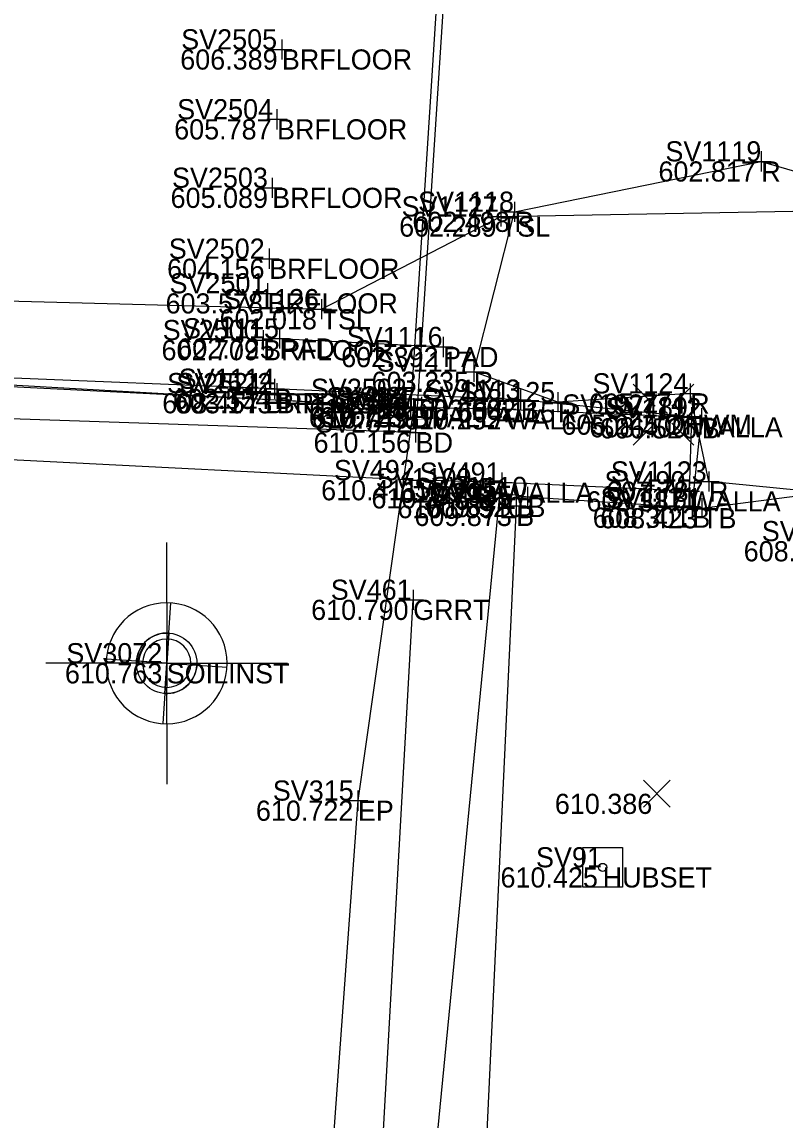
# Model space of a CAD drawing. Extents: x -2 to 1979875, y -2 to 232027.
# Drawn here: x 1978775.86 to 1978794.79, y 231234.17 to 231261.41 of the extents above; entities that cross this region are included whole.
import ezdxf

# ---------------------------------------------------------------- set-up
doc = ezdxf.new("R2010")
doc.units = 0
for name, color, linetype in [('_CIVIL_CONSTRUCTION', 7, 'Continuous'), ('BR_X_SV_Abut', 7, 'Continuous'), ('BR_X_SV_Deck_Floor_Text', 7, 'Continuous'), ('BR_X_SV_Deck_Top', 7, 'Continuous'), ('BR_X_SV_Deck_Top_Text', 7, 'Continuous'), ('DR_X_Erosion_Control', 7, 'Continuous'), ('GE_P_Alignment', 7, 'Continuous'), ('GE_P_Alignment_1000_Stations', 7, 'Continuous'), ('GE_P_Alignment_500_Stations', 7, 'Continuous'), ('GE_X_Alignment', 7, 'Continuous'), ('GE_X_Alignment_1000_Stations', 7, 'Continuous'), ('GE_X_Alignment_100_Curve_Data', 7, 'Continuous'), ('GE_X_Alignment_100_Stations', 7, 'Continuous'), ('GT_Project_Soil_Boring', 7, 'Continuous'), ('HY_X_Water_Edge', 7, 'Continuous'), ('RD_X_Concrete_Pad', 7, 'Continuous'), ('SC_Scratch1', 7, 'Continuous'), ('SV_P_Control_Cells_Set', 7, 'Continuous'), ('SV_X_Control_Cells_Found', 7, 'Continuous'), ('SV_X_Random_Point', 7, 'Continuous'), ('SV_X_Toe_of_Slope', 7, 'Continuous'), ('SV_X_Top_of_Bank', 7, 'Continuous')]:
    doc.layers.add(name, color=color, linetype=linetype)

msp = doc.modelspace()

# ---------------------------------------------------------------- linework, layer by layer
at = {"layer": 'BR_X_SV_Abut'}
for p, q in [((1978761.383, 231253.071), (1978785.768, 231251.859)), ((1978761.397, 231251.268), (1978785.698, 231250.046))]:
    msp.add_line(p, q, dxfattribs=at)
msp.add_lwpolyline([(1978785.768, 231251.859), (1978787.866, 231251.803), (1978792.465, 231251.608), (1978792.413, 231249.77), (1978787.767, 231249.984), (1978785.698, 231250.046)], dxfattribs=at)
at = {"layer": 'BR_X_SV_Deck_Top'}
msp.add_lwpolyline([(1978761.339, 231252.043), (1978764.257, 231294.289), (1978788.348, 231293.277), (1978785.624, 231251.227)], close=True, dxfattribs=at)
at = {"layer": 'DR_X_Erosion_Control'}
msp.add_lwpolyline([(1978787.067, 231252.736), (1978788.074, 231256.704), (1978794.199, 231257.953), (1978799.369, 231256.456), (1978800.674, 231252.04), (1978797.344, 231249.578), (1978792.901, 231250.012), (1978792.436, 231252.197), (1978789.154, 231251.981)], close=True, dxfattribs=at)
at = {"layer": 'GE_P_Alignment'}
msp.add_line((1978782.12, 231252.312), (1978764.845, 231253.02), dxfattribs=at)
for points in [[(1978761.807, 231253.072), (1978774.411, 231252.478), (1978785.5, 231251.852)], [(1978787.063, 231249.844), (1978788.4, 231249.628), (1978792.488, 231249.365), (1978792.72, 231251.581), (1978788.23, 231252.041), (1978782.12, 231252.312)], [(1978788.119, 231249.408), (1978786.943, 231224.352), (1978784.459, 231203.181), (1978783.148, 231179.495), (1978781.259, 231158.933), (1978779.831, 231135.814), (1978779.399, 231114.976), (1978780.51, 231101.208), (1978780.469, 231098.542), (1978778.925, 231080.086), (1978777.811, 231054.63), (1978776.389, 231030.876)]]:
    msp.add_lwpolyline(points, dxfattribs=at)
at = {"layer": 'GE_P_Alignment_1000_Stations'}
msp.add_lwpolyline([(1978779.18, 231099.769), (1978777.975, 231123.065), (1978779.192, 231147.605), (1978781.012, 231172.97), (1978782.386, 231197.771), (1978784.253, 231223.721), (1978785.562, 231247.078)], dxfattribs=at)
at = {"layer": 'GE_X_Alignment_1000_Stations'}
for points in [[(1978787.697, 231292.411), (1978786.77, 231271.728), (1978785.515, 231252.063)], [(1978785.568, 231251.827), (1978784.19, 231242.096), (1978782.784, 231222.648), (1978782.32, 231202.663), (1978780.702, 231177.057), (1978778.946, 231150.803), (1978777.805, 231126.797), (1978776.986, 231106.931), (1978775.705, 231085.257), (1978774.572, 231063.753), (1978773.517, 231041.76), (1978772.029, 231016.51), (1978770.7, 230994.507), (1978769.257, 230972.092), (1978767.73, 230948.595), (1978766.192, 230924.232), (1978764.603, 230899.039), (1978762.827, 230873.547), (1978761.273, 230848.668), (1978759.848, 230822.744), (1978759.345, 230799.915), (1978760.114, 230777.862), (1978762.938, 230755.551), (1978769.839, 230729.514)]]:
    msp.add_lwpolyline(points, dxfattribs=at)
at = {"layer": 'GE_X_Alignment_100_Curve_Data'}
for p, q in [((1978782.305, 231260.981), (1978782.305, 231260.481)), ((1978782.055, 231260.731), (1978782.555, 231260.731)), ((1978782.305, 231260.731), (1978782.305, 231260.731)), ((1978782.185, 231259.248), (1978782.185, 231258.748)), ((1978781.935, 231258.998), (1978782.435, 231258.998)), ((1978782.185, 231258.998), (1978782.185, 231258.998)), ((1978794.199, 231258.203), (1978794.199, 231257.703)), ((1978793.949, 231257.953), (1978794.449, 231257.953)), ((1978794.199, 231257.953), (1978794.199, 231257.953)), ((1978782.066, 231257.549), (1978782.066, 231257.049)), ((1978781.816, 231257.299), (1978782.316, 231257.299)), ((1978782.066, 231257.299), (1978782.066, 231257.299)), ((1978787.737, 231256.836), (1978787.737, 231256.336)), ((1978787.824, 231256.704), (1978788.324, 231256.704)), ((1978788.074, 231256.954), (1978788.074, 231256.454)), ((1978788.074, 231256.704), (1978788.074, 231256.704)), ((1978787.487, 231256.586), (1978787.987, 231256.586)), ((1978787.737, 231256.586), (1978787.737, 231256.586)), ((1978781.99, 231255.789), (1978781.99, 231255.289)), ((1978781.74, 231255.539), (1978782.24, 231255.539)), ((1978781.99, 231255.539), (1978781.99, 231255.539)), ((1978781.951, 231254.93), (1978781.951, 231254.43)), ((1978781.701, 231254.68), (1978782.201, 231254.68)), ((1978781.951, 231254.68), (1978781.951, 231254.68)), ((1978783.289, 231254.537), (1978783.289, 231254.037)), ((1978783.039, 231254.287), (1978783.539, 231254.287)), ((1978783.289, 231254.287), (1978783.289, 231254.287)), ((1978781.841, 231253.77), (1978781.841, 231253.27)), ((1978782.248, 231253.813), (1978782.248, 231253.313)), ((1978781.591, 231253.52), (1978782.091, 231253.52)), ((1978781.841, 231253.52), (1978781.841, 231253.52)), ((1978781.998, 231253.563), (1978782.498, 231253.563)), ((1978782.248, 231253.563), (1978782.248, 231253.563)), ((1978786.305, 231253.599), (1978786.305, 231253.099)), ((1978786.055, 231253.349), (1978786.555, 231253.349)), ((1978786.305, 231253.349), (1978786.305, 231253.349)), ((1978787.067, 231252.986), (1978787.067, 231252.486)), ((1978786.817, 231252.736), (1978787.317, 231252.736)), ((1978787.067, 231252.736), (1978787.067, 231252.736)), ((1978781.89, 231252.454), (1978781.89, 231251.954)), ((1978782.12, 231252.562), (1978782.12, 231252.062)), ((1978782.178, 231252.453), (1978782.178, 231251.953)), ((1978792.436, 231252.447), (1978792.436, 231251.947)), ((1978781.64, 231252.204), (1978782.14, 231252.204)), ((1978781.87, 231252.312), (1978782.37, 231252.312)), ((1978781.89, 231252.204), (1978781.89, 231252.204)), ((1978781.928, 231252.203), (1978782.428, 231252.203)), ((1978782.12, 231252.312), (1978782.12, 231252.312)), ((1978782.178, 231252.203), (1978782.178, 231252.203)), ((1978785.5, 231252.102), (1978785.5, 231251.602)), ((1978785.515, 231252.313), (1978785.515, 231251.813)), ((1978785.568, 231252.077), (1978785.568, 231251.577)), ((1978785.768, 231252.109), (1978785.768, 231251.609)), ((1978788.23, 231252.291), (1978788.23, 231251.791)), ((1978789.154, 231252.231), (1978789.154, 231251.731)), ((1978792.186, 231252.197), (1978792.686, 231252.197)), ((1978792.436, 231252.197), (1978792.436, 231252.197)), ((1978785.25, 231251.852), (1978785.75, 231251.852)), ((1978785.265, 231252.063), (1978785.765, 231252.063)), ((1978785.318, 231251.827), (1978785.818, 231251.827)), ((1978785.5, 231251.852), (1978785.5, 231251.852)), ((1978785.515, 231252.063), (1978785.515, 231252.063)), ((1978785.518, 231251.859), (1978786.018, 231251.859)), ((1978785.568, 231251.827), (1978785.568, 231251.827)), ((1978785.768, 231251.859), (1978785.768, 231251.859)), ((1978787.616, 231251.803), (1978788.116, 231251.803)), ((1978787.866, 231252.053), (1978787.866, 231251.553)), ((1978787.866, 231251.803), (1978787.866, 231251.803)), ((1978787.98, 231252.041), (1978788.48, 231252.041)), ((1978788.23, 231252.041), (1978788.23, 231252.041)), ((1978788.904, 231251.981), (1978789.404, 231251.981)), ((1978789.154, 231251.981), (1978789.154, 231251.981)), ((1978792.465, 231251.858), (1978792.465, 231251.358)), ((1978792.72, 231251.831), (1978792.72, 231251.331)), ((1978792.215, 231251.608), (1978792.715, 231251.608)), ((1978792.465, 231251.608), (1978792.465, 231251.608)), ((1978792.47, 231251.581), (1978792.97, 231251.581)), ((1978792.72, 231251.581), (1978792.72, 231251.581)), ((1978785.624, 231251.477), (1978785.624, 231250.977)), ((1978785.374, 231251.227), (1978785.874, 231251.227)), ((1978785.624, 231251.227), (1978785.624, 231251.227)), ((1978785.698, 231250.296), (1978785.698, 231249.796)), ((1978787.767, 231250.234), (1978787.767, 231249.734)), ((1978792.901, 231250.262), (1978792.901, 231249.762)), ((1978785.448, 231250.046), (1978785.948, 231250.046)), ((1978785.698, 231250.046), (1978785.698, 231250.046)), ((1978787.063, 231250.094), (1978787.063, 231249.594)), ((1978787.517, 231249.984), (1978788.017, 231249.984)), ((1978787.767, 231249.984), (1978787.767, 231249.984)), ((1978792.413, 231250.02), (1978792.413, 231249.52)), ((1978792.651, 231250.012), (1978793.151, 231250.012)), ((1978792.901, 231250.012), (1978792.901, 231250.012)), ((1978786.813, 231249.844), (1978787.313, 231249.844)), ((1978787.063, 231249.844), (1978787.063, 231249.844)), ((1978787.694, 231249.851), (1978787.694, 231249.351)), ((1978788.119, 231249.658), (1978788.119, 231249.158)), ((1978788.15, 231249.628), (1978788.65, 231249.628)), ((1978788.4, 231249.878), (1978788.4, 231249.378)), ((1978788.4, 231249.628), (1978788.4, 231249.628)), ((1978792.163, 231249.77), (1978792.663, 231249.77)), ((1978792.413, 231249.77), (1978792.413, 231249.77)), ((1978787.444, 231249.601), (1978787.944, 231249.601)), ((1978787.694, 231249.601), (1978787.694, 231249.601)), ((1978787.869, 231249.408), (1978788.369, 231249.408)), ((1978788.119, 231249.408), (1978788.119, 231249.408)), ((1978792.238, 231249.365), (1978792.738, 231249.365)), ((1978792.479, 231249.351), (1978792.979, 231249.351)), ((1978792.488, 231249.615), (1978792.488, 231249.115)), ((1978792.488, 231249.365), (1978792.488, 231249.365)), ((1978792.729, 231249.601), (1978792.729, 231249.101)), ((1978792.729, 231249.351), (1978792.729, 231249.351)), ((1978785.562, 231247.328), (1978785.562, 231246.828)), ((1978785.312, 231247.078), (1978785.812, 231247.078)), ((1978785.562, 231247.078), (1978785.562, 231247.078)), ((1978784.19, 231242.346), (1978784.19, 231241.846)), ((1978783.94, 231242.096), (1978784.44, 231242.096)), ((1978784.19, 231242.096), (1978784.19, 231242.096))]:
    msp.add_line(p, q, dxfattribs=at)
at = {"layer": 'GT_Project_Soil_Boring'}
for p, q in [((1978779.449, 231245.503), (1978779.549, 231247)), ((1978779.499, 231246.251), (1978779.449, 231245.503)), ((1978779.449, 231245.503), (1978777.952, 231245.603)), ((1978779.449, 231245.503), (1978778.701, 231245.553)), ((1978779.449, 231245.503), (1978779.349, 231244.006)), ((1978779.399, 231244.755), (1978779.449, 231245.503)), ((1978779.449, 231245.503), (1978780.946, 231245.403)), ((1978779.449, 231245.503), (1978780.197, 231245.453))]:
    msp.add_line(p, q, dxfattribs=at)
msp.add_circle((1978779.449, 231245.503), 0.75, dxfattribs=at)
for start, end in [(86.1708, 176.1708), (266.1708, 356.1708)]:
    msp.add_arc((1978779.449, 231245.503), 0.75, start, end, dxfattribs=at)
at = {"layer": 'HY_X_Water_Edge'}
msp.add_lwpolyline([(1978710.396, 231262.363), (1978725.371, 231260.246), (1978739.363, 231256.715), (1978742.039, 231254.081), (1978754.512, 231255.046), (1978783.289, 231254.287), (1978787.737, 231256.586), (1978799.967, 231256.811), (1978817.09, 231257.737), (1978832.082, 231262.479)], dxfattribs=at)
at = {"layer": 'RD_X_Concrete_Pad'}
msp.add_lwpolyline([(1978782.248, 231253.563), (1978786.305, 231253.349)], dxfattribs=at)
at = {"layer": 'SC_Scratch1'}
for p, q in [((1978779.449, 231247.003), (1978779.449, 231248.503)), ((1978779.449, 231247.003), (1978779.449, 231246.103)), ((1978779.449, 231245.503), (1978779.449, 231246.103)), ((1978777.949, 231245.503), (1978776.449, 231245.503)), ((1978778.849, 231245.503), (1978777.949, 231245.503)), ((1978779.449, 231245.503), (1978778.849, 231245.503)), ((1978779.449, 231245.503), (1978780.049, 231245.503)), ((1978779.449, 231245.503), (1978779.449, 231244.903)), ((1978780.049, 231245.503), (1978780.949, 231245.503)), ((1978780.949, 231245.503), (1978782.449, 231245.503)), ((1978779.449, 231244.003), (1978779.449, 231244.903)), ((1978779.449, 231244.003), (1978779.449, 231242.503))]:
    msp.add_line(p, q, dxfattribs=at)
msp.add_lwpolyline([(1978787.694, 231249.601), (1978785.48, 231226.833), (1978784.558, 231206.407), (1978783.016, 231187.193), (1978782.112, 231167.584), (1978780.51, 231145.937), (1978779.287, 231125.907), (1978778.425, 231108.773), (1978777.775, 231087.524), (1978776.748, 231064.782), (1978775.35, 231040.582), (1978774.462, 231016.281), (1978772.549, 230990.683), (1978771.051, 230965.635), (1978769.086, 230942.407), (1978767.324, 230917.989), (1978765.95, 230893.701), (1978764.896, 230870.53), (1978763.088, 230848.633), (1978761.583, 230826.273), (1978760.498, 230804.271), (1978761.5, 230780.247), (1978763.845, 230755.469), (1978770.352, 230731.454)], dxfattribs=at)
for radius, start, end in [(1.5, 90, 180), (1.5, 0, 90), (0.6, 90, 180), (0.6, 0, 90), (1.5, 180, 270), (0.6, 180, 270), (0.6, 270, 0), (1.5, 270, 0)]:
    msp.add_arc((1978779.449, 231245.503), radius, start, end, dxfattribs=at)
at = {"layer": 'SV_P_Control_Cells_Set'}
msp.add_lwpolyline([(1978789.77, 231240.936), (1978790.76, 231240.936), (1978790.76, 231239.945), (1978789.77, 231239.945), (1978789.77, 231240.936)], dxfattribs=at)
msp.add_lwpolyline([(1978789.77, 231240.936), (1978790.76, 231240.936), (1978790.76, 231239.945), (1978789.77, 231239.945), (1978789.77, 231240.936)], dxfattribs=at)
msp.add_lwpolyline([(1978789.77, 231240.936), (1978790.76, 231240.936), (1978790.76, 231239.945), (1978789.77, 231239.945), (1978789.77, 231240.936)], dxfattribs=at)
msp.add_circle((1978790.265, 231240.44), 0.1, dxfattribs=at)
msp.add_circle((1978790.265, 231240.44), 0.1, dxfattribs=at)
msp.add_circle((1978790.265, 231240.44), 0.1, dxfattribs=at)
at = {"layer": 'SV_X_Control_Cells_Found'}
for p, q in [((1978791.021, 231252.425), (1978791.568, 231251.878)), ((1978791.984, 231251.878), (1978792.53, 231252.425)), ((1978791.021, 231250.916), (1978791.568, 231251.462)), ((1978791.984, 231251.462), (1978792.53, 231250.916))]:
    msp.add_line(p, q, dxfattribs=at)
msp.add_circle((1978791.776, 231251.673), 0.085, dxfattribs=at)
at = {"layer": 'SV_X_Random_Point'}
for p, q in [((1978791.277, 231241.932), (1978791.943, 231242.6)), ((1978791.277, 231242.6), (1978791.943, 231241.932))]:
    msp.add_line(p, q, dxfattribs=at)
at = {"layer": 'SV_X_Toe_of_Slope'}
msp.add_lwpolyline([(1978783.289, 231254.287), (1978787.737, 231256.586), (1978799.967, 231256.811), (1978817.09, 231257.737), (1978832.082, 231262.479), (1978831.856, 231267.326), (1978861.367, 231270.387), (1978875.304, 231272.806), (1978884.386, 231282.392), (1978891.721, 231292.42), (1978902.966, 231322.566)], dxfattribs=at)
at = {"layer": 'SV_X_Top_of_Bank'}
msp.add_lwpolyline([(1978792.729, 231249.351), (1978802.059, 231250.56), (1978809.026, 231251.174), (1978824.702, 231257.152), (1978834.668, 231262.265), (1978843.76, 231264.082), (1978857.569, 231267.988), (1978870.834, 231267.898), (1978882.845, 231275.772), (1978894.192, 231280.826), (1978903.719, 231297.628)], dxfattribs=at)

# ---------------------------------------------------------------- texts
at = {"layer": '_CIVIL_CONSTRUCTION'}
for s, p in [('602.817', (1978791.648, 231257.453)), ('602.498', (1978785.544, 231256.204)), ('602.289', (1978785.216, 231256.086)), ('602.018', (1978780.759, 231253.787)), ('602.725', (1978779.713, 231253.063)), ('602.392', (1978783.777, 231252.849)), ('603.235', (1978784.532, 231252.236)), ('602.554', (1978779.604, 231251.812)), ('605.774', (1978789.92, 231251.697)), ('610.763', (1978782.975, 231251.352)), ('610.738', (1978782.985, 231251.563)), ('610.749', (1978783.047, 231251.327)), ('603.602', (1978785.702, 231251.541)), ('604.115', (1978786.67, 231251.481)), ('605.245', (1978789.241, 231251.173)), ('606.526', (1978790.188, 231251.081)), ('607.787', (1978790.35, 231249.512)), ('610.345', (1978784.528, 231249.344)), ('609.920', (1978785.87, 231249.128)), ('610.059', (1978785.173, 231249.101)), ('609.873', (1978785.594, 231248.908)), ('608.301', (1978790.018, 231248.865)), ('608.423', (1978790.204, 231248.851)), ('608.187', (1978793.764, 231248.032)), ('610.790', (1978783.032, 231246.578)), ('610.763', (1978776.924, 231245.003)), ('610.386', (1978789.078, 231241.766)), ('610.722', (1978781.662, 231241.596)), ('610.425', (1978787.73, 231239.94)), ('610.425', (1978787.73, 231239.94)), ('610.425', (1978787.73, 231239.94))]:
    msp.add_text(s, height=0.5, dxfattribs=at).set_placement(p)
at = {"layer": 'BR_X_SV_Deck_Floor_Text'}
for s, p in [('SV2505', (1978779.808, 231260.731)), ('606.389', (1978779.784, 231260.231)), ('BRFLOOR', (1978782.305, 231260.231)), ('SV2504', (1978779.708, 231258.998)), ('605.787', (1978779.634, 231258.498)), ('BRFLOOR', (1978782.185, 231258.498)), ('SV2503', (1978779.58, 231257.299)), ('605.089', (1978779.545, 231256.799)), ('BRFLOOR', (1978782.066, 231256.799)), ('SV2502', (1978779.5, 231255.539)), ('604.156', (1978779.458, 231255.039)), ('BRFLOOR', (1978781.99, 231255.039)), ('SV2501', (1978779.519, 231254.68)), ('603.578', (1978779.421, 231254.18)), ('BRFLOOR', (1978781.951, 231254.18)), ('SV2500', (1978779.349, 231253.52)), ('602.709', (1978779.32, 231253.02)), ('BRFLOOR', (1978781.841, 231253.02)), ('SV2521', (1978779.458, 231252.204)), ('SV2522', (1978779.688, 231252.203)), ('608.457', (1978779.339, 231251.704)), ('603.143', (1978779.653, 231251.703)), ('BRFLOOR', (1978781.89, 231251.704)), ('BRFLOOR', (1978782.178, 231251.703))]:
    msp.add_text(s, height=0.5, dxfattribs=at).set_placement(p)
at = {"layer": 'BR_X_SV_Deck_Top_Text'}
for s, p in [('SV2512', (1978783.134, 231251.227)), ('610.156', (1978783.092, 231250.727)), ('BD', (1978785.624, 231250.727))]:
    msp.add_text(s, height=0.5, dxfattribs=at).set_placement(p)
at = {"layer": 'GE_P_Alignment_500_Stations'}
for s, p in [('SV487', (1978783.643, 231251.859)), ('SV488', (1978785.763, 231251.803)), ('SV489', (1978790.371, 231251.608)), ('610.289', (1978783.247, 231251.359)), ('610.252', (1978785.338, 231251.303)), ('WALLA', (1978785.768, 231251.359)), ('WALLA', (1978787.866, 231251.303)), ('608.400', (1978789.935, 231251.108)), ('WALLA', (1978792.465, 231251.108)), ('SV492', (1978783.597, 231250.046)), ('SV491', (1978785.724, 231249.984)), ('SV490', (1978790.309, 231249.77)), ('610.411', (1978783.28, 231249.546)), ('610.235', (1978785.232, 231249.484)), ('WALLA', (1978785.698, 231249.546)), ('WALLA', (1978787.767, 231249.484)), ('608.387', (1978789.862, 231249.27)), ('WALLA', (1978792.413, 231249.27))]:
    msp.add_text(s, height=0.5, dxfattribs=at).set_placement(p)
at = {"layer": 'GE_X_Alignment'}
for s, p in [('SV1119', (1978791.821, 231257.953)), ('SV1127', (1978785.276, 231256.586)), ('SV1118', (1978785.686, 231256.704)), ('SV1126', (1978780.847, 231254.287)), ('SV1115', (1978779.855, 231253.563)), ('SV1116', (1978783.915, 231253.349)), ('SV1117', (1978784.658, 231252.736)), ('SV1114', (1978779.747, 231252.312)), ('SV1124', (1978790.011, 231252.197)), ('SV2502', (1978783.025, 231252.063)), ('SV419', (1978783.406, 231251.852)), ('SV1113', (1978785.847, 231252.041)), ('SV1125', (1978786.709, 231251.981)), ('SV314', (1978783.479, 231251.827)), ('SV1927', (1978789.263, 231251.673)), ('SV1112', (1978790.334, 231251.581)), ('SV1123', (1978790.467, 231250.012)), ('SV1109', (1978784.633, 231249.844)), ('SV365', (1978785.585, 231249.601)), ('SV935', (1978786.01, 231249.408)), ('SV1110', (1978786.012, 231249.628)), ('SV1111', (1978790.212, 231249.365)), ('SV1181', (1978790.349, 231249.351)), ('SV958', (1978794.212, 231248.532)), ('SV461', (1978783.519, 231247.078)), ('SV3072', (1978776.959, 231245.503)), ('SV315', (1978782.081, 231242.096)), ('SV91', (1978788.61, 231240.44)), ('SV91', (1978788.61, 231240.44)), ('SV91', (1978788.61, 231240.44))]:
    msp.add_text(s, height=0.5, dxfattribs=at).set_placement(p)
at = {"layer": 'GE_X_Alignment_100_Stations'}
for s, p in [('R', (1978794.199, 231257.453)), ('R', (1978788.074, 231256.204)), ('TSL', (1978787.737, 231256.086)), ('TSL', (1978783.289, 231253.787)), ('PAD', (1978782.248, 231253.063)), ('PAD', (1978786.305, 231252.849)), ('R', (1978787.067, 231252.236)), ('B', (1978782.12, 231251.812)), ('R', (1978792.436, 231251.697)), ('B', (1978785.5, 231251.352)), ('EP', (1978785.515, 231251.563)), ('EP', (1978785.568, 231251.327)), ('B', (1978788.23, 231251.541)), ('R', (1978789.154, 231251.481)), ('OHWM', (1978791.776, 231251.173)), ('B', (1978792.72, 231251.081)), ('R', (1978792.901, 231249.512)), ('B', (1978787.063, 231249.344)), ('B', (1978788.4, 231249.128)), ('EB', (1978787.694, 231249.101)), ('B', (1978788.119, 231248.908)), ('B', (1978792.488, 231248.865)), ('TB', (1978792.729, 231248.851)), ('GRRT', (1978785.562, 231246.578)), ('SOILINST', (1978779.449, 231245.003)), ('EP', (1978784.19, 231241.596)), ('HUBSET', (1978790.265, 231239.94)), ('HUBSET', (1978790.265, 231239.94)), ('HUBSET', (1978790.265, 231239.94))]:
    msp.add_text(s, height=0.5, dxfattribs=at).set_placement(p)

doc.saveas('drawing.dxf')
